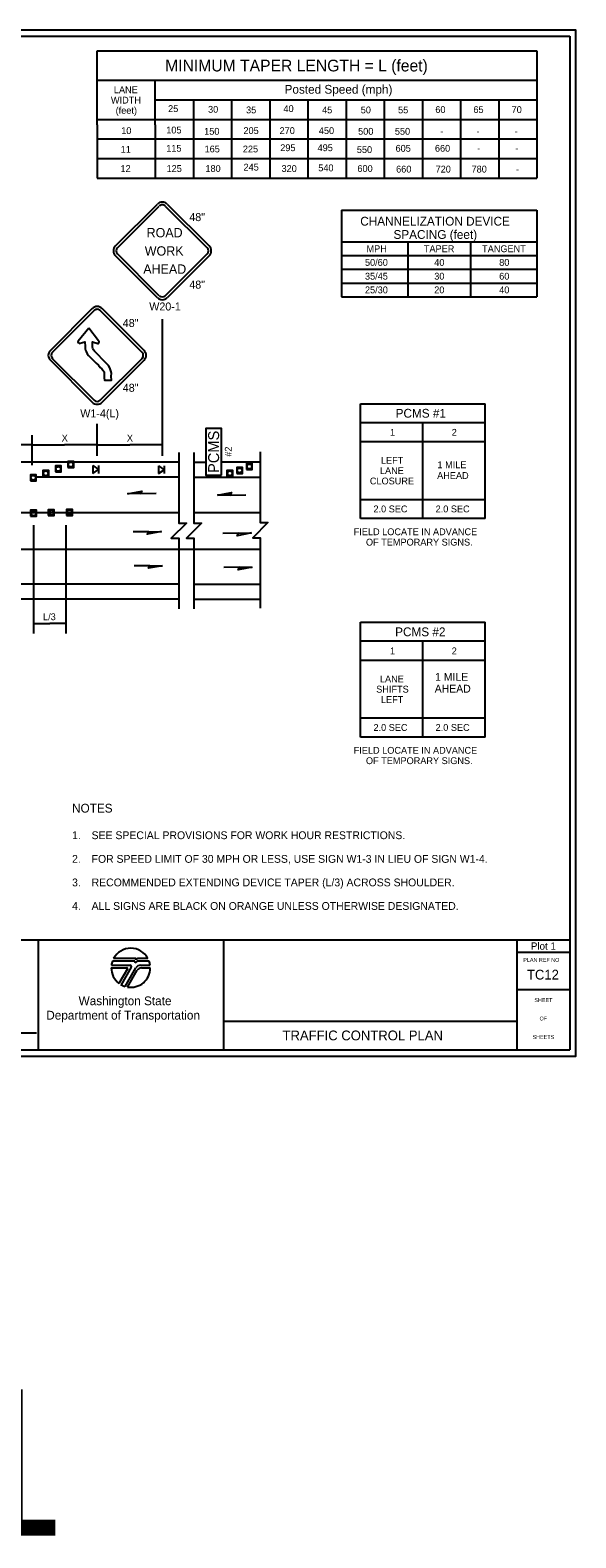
# Model space of a CAD drawing. Extents: x 99988 to 100172, y 99995 to 100047.
# Drawn here: x 100010.23 to 100015.81, y 99995.01 to 100010.44 of the extents above; entities that cross this region are included whole.
import ezdxf

# ---------------------------------------------------------------- set-up
doc = ezdxf.new("R2010")
doc.units = 0
for name, color, linetype in [('Default', 7, 'Continuous'), ('Level 15', 7, 'Continuous'), ('Level 20', 7, 'Continuous'), ('SH_DE_DetailBody1Text', 7, 'Continuous'), ('SH_GI_PlotLimits', 7, 'Continuous'), ('SH_GI_SheetBorder', 7, 'Continuous'), ('SH_GI_SheetLocationText', 7, 'Continuous'), ('SH_GI_SheetTextInCells', 7, 'Continuous'), ('SH_GI_TitleBlockText', 7, 'Continuous'), ('SH_GI_TrafficMvmntArrowRt1Lane', 7, 'Continuous'), ('SH_GI_WSDOTLogo', 7, 'Continuous'), ('SH_TI_ChanSpacing25to70Note', 7, 'Continuous'), ('SH_TI_MinTaperLength25to60Note', 7, 'Continuous'), ('TR_SN_WarningSigns', 7, 'Continuous'), ('TR_WZ_PortableChangeMessageSign', 7, 'Continuous'), ('TR_WZ_TrafficSafetyCone', 7, 'Continuous'), ('TR_WZ_WorkZoneDetails', 7, 'Continuous')]:
    doc.layers.add(name, color=color, linetype=linetype)

msp = doc.modelspace()

# ---------------------------------------------------------------- linework, layer by layer
at = {"layer": 'Default'}
for p, q in [((100010.867, 100005.98), (100010.925, 100005.94)), ((100010.867, 100005.98), (100010.867, 100005.9)), ((100010.925, 100005.98), (100010.925, 100005.9)), ((100011.54, 100005.979), (100011.598, 100005.938)), ((100011.54, 100005.979), (100011.54, 100005.898)), ((100011.598, 100005.979), (100011.598, 100005.898)), ((100010.867, 100005.9), (100010.925, 100005.94)), ((100011.54, 100005.898), (100011.598, 100005.938)), ((100011.748, 100005.496), (100005.446, 100005.496)), ((100012.582, 100005.496), (100011.903, 100005.496)), ((100012.582, 100005.121), (100002.425, 100005.121))]:
    msp.add_line(p, q, dxfattribs=at)
at = {"layer": 'Level 15'}
for p, q in [((100010.247, 100006.192), (100009.857, 100006.192)), ((100010.247, 100006.192), (100010.58, 100006.192)), ((100010.913, 100006.192), (100010.58, 100006.192)), ((100010.913, 100006.192), (100011.247, 100006.192)), ((100011.58, 100006.192), (100011.247, 100006.192)), ((100010.263, 100004.363), (100010.429, 100004.363)), ((100010.596, 100004.363), (100010.429, 100004.363))]:
    msp.add_line(p, q, dxfattribs=at)
at = {"layer": 'SH_GI_PlotLimits'}
msp.add_lwpolyline([(99999.312, 99999.937), (100015.812, 99999.937), (100015.812, 100010.437), (99999.312, 100010.437)], close=True, dxfattribs=at)
at = {"layer": 'SH_GI_SheetBorder'}
for p, q in [((100000, 100010.375), (100015.75, 100010.375)), ((100015.75, 100010.375), (100015.75, 100000)), ((100000, 100001.126), (100015.75, 100001.126)), ((100010.309, 100001.126), (100010.309, 100000)), ((100012.205, 100001.126), (100012.205, 100000)), ((100015.208, 100001.126), (100015.208, 100000)), ((100015.208, 100001.001), (100015.75, 100001.001)), ((100015.208, 100000.618), (100015.75, 100000.618)), ((100012.205, 100000.295), (100015.208, 100000.295)), ((100009.78, 100000.173), (100010.291, 100000.173)), ((100000, 100000), (100015.75, 100000))]:
    msp.add_line(p, q, dxfattribs=at)
at = {"layer": 'SH_GI_TrafficMvmntArrowRt1Lane'}
for p, q in [((100011.355, 100005.694), (100011.516, 100005.697)), ((100012.274, 100005.679), (100012.435, 100005.682)), ((100011.441, 100005.304), (100011.28, 100005.302)), ((100012.36, 100005.289), (100012.199, 100005.287)), ((100011.451, 100004.955), (100011.29, 100004.953)), ((100012.37, 100004.94), (100012.209, 100004.937))]:
    msp.add_line(p, q, dxfattribs=at)
for points in [[(100011.224, 100005.693), (100011.37, 100005.72), (100011.355, 100005.694)], [(100012.143, 100005.678), (100012.289, 100005.705), (100012.274, 100005.679)], [(100011.572, 100005.306), (100011.426, 100005.278), (100011.441, 100005.304)], [(100012.491, 100005.291), (100012.345, 100005.263), (100012.36, 100005.289)], [(100011.582, 100004.956), (100011.437, 100004.929), (100011.451, 100004.955)], [(100012.501, 100004.941), (100012.355, 100004.914), (100012.37, 100004.94)]]:
    msp.add_lwpolyline(points, close=True, dxfattribs=at)
at = {"layer": 'SH_GI_WSDOTLogo'}
for p, q in [((100011.289, 100000.909), (100011.07, 100000.909)), ((100011.303, 100000.935), (100011.081, 100000.935)), ((100011.433, 100000.935), (100011.335, 100000.935)), ((100011.445, 100000.909), (100011.343, 100000.909)), ((100011.343, 100000.909), (100011.343, 100000.909)), ((100011.057, 100000.84), (100011.215, 100000.84)), ((100011.059, 100000.866), (100011.25, 100000.866)), ((100011.222, 100000.828), (100011.136, 100000.681)), ((100011.261, 100000.846), (100011.157, 100000.667)), ((100011.199, 100000.649), (100011.309, 100000.839)), ((100011.224, 100000.643), (100011.324, 100000.816)), ((100011.356, 100000.866), (100011.456, 100000.866)), ((100011.365, 100000.839), (100011.457, 100000.839))]:
    msp.add_line(p, q, dxfattribs=at)
for centre, radius, start, end in [((100011.257, 100000.84), 0.2, 28.4787, 151.532), ((100011.257, 100000.84), 0.2, 159.696, 172.5057), ((100011.289, 100000.895), 0.0148, 327.8418, 89.9985), ((100011.343, 100000.861), 0.0484, 89.9953, 147.8238), ((100011.303, 100000.926), 0.00903, 329.8742, 90.0033), ((100011.335, 100000.907), 0.0287, 90.0072, 148.1676), ((100011.257, 100000.84), 0.2, 7.4943, 20.2941), ((100011.257, 100000.84), 0.2, 179.9986, 232.8433), ((100011.215, 100000.832), 0.0082, 329.7436, 90), ((100011.257, 100000.84), 0.2, 260.5455, 359.8086), ((100011.25, 100000.853), 0.0131, 329.7683, 90), ((100011.356, 100000.812), 0.0542, 90, 149.9974), ((100011.365, 100000.792), 0.0476, 90, 150.0543), ((100011.257, 100000.84), 0.2, 239.7929, 253.0448)]:
    msp.add_arc(centre, radius, start, end, dxfattribs=at)
at = {"layer": 'SH_TI_ChanSpacing25to70Note'}
for p, q in [((100013.414, 100008.595), (100013.414, 100007.709)), ((100013.414, 100008.595), (100015.414, 100008.595)), ((100015.414, 100008.595), (100015.414, 100007.709)), ((100013.414, 100008.27), (100015.414, 100008.27)), ((100014.097, 100007.709), (100014.097, 100008.27)), ((100014.739, 100007.709), (100014.739, 100008.27)), ((100013.414, 100008.13), (100015.414, 100008.13)), ((100013.414, 100007.99), (100015.414, 100007.99)), ((100013.414, 100007.849), (100015.414, 100007.849)), ((100013.414, 100007.709), (100015.414, 100007.709))]:
    msp.add_line(p, q, dxfattribs=at)
at = {"layer": 'SH_TI_MinTaperLength25to60Note'}
for p, q in [((100010.914, 100010.227), (100015.414, 100010.227)), ((100010.914, 100009.469), (100010.914, 100010.227)), ((100015.414, 100010.227), (100015.414, 100008.924)), ((100010.914, 100009.924), (100015.414, 100009.924)), ((100011.507, 100009.469), (100011.507, 100009.924)), ((100011.507, 100009.724), (100015.414, 100009.724)), ((100011.898, 100009.724), (100011.898, 100008.924)), ((100012.288, 100009.724), (100012.288, 100008.924)), ((100012.679, 100009.724), (100012.679, 100008.924)), ((100013.07, 100009.724), (100013.07, 100008.924)), ((100013.46, 100009.724), (100013.46, 100008.924)), ((100013.851, 100009.724), (100013.851, 100008.924)), ((100014.242, 100009.724), (100014.242, 100008.924)), ((100014.632, 100009.724), (100014.632, 100008.924)), ((100015.023, 100009.724), (100015.023, 100008.924)), ((100010.914, 100009.524), (100015.414, 100009.524)), ((100010.914, 100009.469), (100010.914, 100008.924)), ((100011.507, 100009.469), (100011.507, 100008.924)), ((100010.914, 100009.324), (100015.414, 100009.324)), ((100010.914, 100009.124), (100015.414, 100009.124)), ((100010.914, 100008.924), (100015.414, 100008.924))]:
    msp.add_line(p, q, dxfattribs=at)
at = {"layer": 'TR_SN_WarningSigns'}
for p, q in [((100011.1, 100008.229), (100011.529, 100008.657)), ((100011.121, 100008.209), (100011.549, 100008.637)), ((100011.61, 100008.637), (100012.039, 100008.209)), ((100011.631, 100008.657), (100012.059, 100008.229)), ((100011.549, 100007.719), (100011.121, 100008.148)), ((100012.039, 100008.148), (100011.61, 100007.719)), ((100011.529, 100007.699), (100011.1, 100008.127)), ((100012.059, 100008.127), (100011.631, 100007.699)), ((100010.862, 100007.588), (100010.434, 100007.16)), ((100010.883, 100007.568), (100010.454, 100007.139)), ((100011.372, 100007.139), (100010.944, 100007.568)), ((100011.393, 100007.16), (100010.964, 100007.588)), ((100010.434, 100007.058), (100010.862, 100006.63)), ((100010.454, 100007.078), (100010.883, 100006.65)), ((100010.944, 100006.65), (100011.372, 100007.078)), ((100010.964, 100006.63), (100011.393, 100007.058))]:
    msp.add_line(p, q, dxfattribs=at)
msp.add_lwpolyline([(100010.828, 100007.386), (100010.718, 100007.254), (100010.716, 100007.247), (100010.721, 100007.237), (100010.731, 100007.229), (100010.74, 100007.232), (100010.788, 100007.246), (100010.789, 100007.198), (100010.79, 100007.176), (100010.794, 100007.162), (100010.799, 100007.149), (100010.812, 100007.126), (100010.825, 100007.109), (100010.84, 100007.09), (100010.859, 100007.073), (100010.88, 100007.052), (100010.903, 100007.028), (100010.925, 100007.007), (100010.945, 100006.986), (100010.962, 100006.97), (100010.976, 100006.954), (100010.983, 100006.941), (100010.986, 100006.923), (100010.983, 100006.897), (100010.985, 100006.88), (100010.987, 100006.856), (100011.059, 100006.856), (100011.057, 100006.896), (100011.059, 100006.922), (100011.056, 100006.94), (100011.05, 100006.96), (100011.042, 100006.982), (100011.029, 100007.006), (100011.005, 100007.03), (100010.886, 100007.153), (100010.874, 100007.167), (100010.868, 100007.178), (100010.866, 100007.192), (100010.864, 100007.201), (100010.865, 100007.247), (100010.919, 100007.229), (100010.925, 100007.231), (100010.93, 100007.236), (100010.935, 100007.247), (100010.934, 100007.252), (100010.927, 100007.258)], close=True, dxfattribs=at)
for centre, radius, start, end in [((100011.58, 100008.606), 0.0721, 44.9963, 134.9997), ((100011.58, 100008.606), 0.0433, 44.9963, 134.9997), ((100011.151, 100008.178), 0.0721, 134.9966, 224.9936), ((100011.151, 100008.178), 0.0433, 134.9966, 224.9936), ((100012.008, 100008.178), 0.0433, 314.9994, 44.9948), ((100012.008, 100008.178), 0.0721, 314.9994, 44.9948), ((100011.58, 100007.75), 0.0721, 225, 314.9996), ((100011.58, 100007.75), 0.0433, 225, 314.9996), ((100010.913, 100007.537), 0.0721, 44.9963, 134.9997), ((100010.913, 100007.537), 0.0433, 44.9963, 134.9997), ((100010.485, 100007.109), 0.0721, 134.9966, 224.9936), ((100010.485, 100007.109), 0.0433, 134.9966, 224.9936), ((100011.342, 100007.109), 0.0433, 314.9994, 44.9948), ((100011.342, 100007.109), 0.0721, 314.9994, 44.9948), ((100010.913, 100006.681), 0.0721, 225, 314.9996), ((100010.913, 100006.681), 0.0433, 225, 314.9996)]:
    msp.add_arc(centre, radius, start, end, dxfattribs=at)
at = {"layer": 'TR_WZ_PortableChangeMessageSign'}
msp.add_lwpolyline([(100012.185, 100005.881), (100012.185, 100006.361), (100012.025, 100006.361), (100012.025, 100005.881)], close=True, dxfattribs=at)
at = {"layer": 'TR_WZ_TrafficSafetyCone'}
for points in [[(100010.485, 100005.916), (100010.545, 100005.916), (100010.545, 100005.977), (100010.485, 100005.977)], [(100010.613, 100005.962), (100010.674, 100005.962), (100010.674, 100006.023), (100010.613, 100006.023)], [(100012.44, 100005.941), (100012.501, 100005.941), (100012.501, 100006.001), (100012.44, 100006.001)], [(100010.229, 100005.825), (100010.29, 100005.825), (100010.29, 100005.886), (100010.229, 100005.886)], [(100010.356, 100005.871), (100010.417, 100005.871), (100010.417, 100005.931), (100010.356, 100005.931)], [(100012.241, 100005.87), (100012.302, 100005.87), (100012.302, 100005.931), (100012.241, 100005.931)], [(100012.341, 100005.901), (100012.401, 100005.901), (100012.401, 100005.962), (100012.341, 100005.962)], [(100010.232, 100005.462), (100010.293, 100005.462), (100010.293, 100005.523), (100010.232, 100005.523)], [(100010.413, 100005.468), (100010.474, 100005.468), (100010.474, 100005.529), (100010.413, 100005.529)], [(100010.599, 100005.471), (100010.66, 100005.471), (100010.66, 100005.531), (100010.599, 100005.531)]]:
    msp.add_lwpolyline(points, close=True, dxfattribs=at)
for centre in [(100010.643, 100005.992), (100012.471, 100005.971), (100010.259, 100005.856), (100010.387, 100005.901), (100010.515, 100005.947), (100012.272, 100005.901), (100012.371, 100005.931), (100010.263, 100005.492), (100010.444, 100005.499), (100010.629, 100005.501)]:
    msp.add_circle(centre, 0.0244, dxfattribs=at)
at = {"layer": 'TR_WZ_WorkZoneDetails'}
for p, q in [((100011.58, 100006.08), (100011.58, 100007.478)), ((100013.61, 100006.614), (100014.883, 100006.614)), ((100013.61, 100005.439), (100013.61, 100006.614)), ((100014.883, 100005.439), (100014.883, 100006.614)), ((100010.247, 100005.986), (100010.247, 100006.292)), ((100010.913, 100006.08), (100010.913, 100006.408)), ((100014.883, 100006.418), (100013.61, 100006.418)), ((100014.246, 100005.439), (100014.246, 100006.418)), ((100014.883, 100006.223), (100013.61, 100006.223)), ((100011.748, 100006.014), (100008.204, 100006.014)), ((100011.903, 100006.014), (100012.019, 100006.014)), ((100012.195, 100006.02), (100012.582, 100006.02)), ((100011.748, 100005.861), (100010.29, 100005.861)), ((100011.903, 100005.861), (100012.577, 100005.861)), ((100013.61, 100005.635), (100014.883, 100005.635)), ((100010.263, 100004.263), (100010.263, 100005.371)), ((100010.596, 100004.263), (100010.596, 100005.371)), ((100014.883, 100005.439), (100013.61, 100005.439)), ((100011.748, 100004.768), (100002.428, 100004.768)), ((100011.903, 100004.768), (100012.584, 100004.768)), ((100011.748, 100004.614), (100002.431, 100004.614)), ((100011.903, 100004.614), (100012.581, 100004.614)), ((100013.61, 100004.377), (100014.883, 100004.377)), ((100013.61, 100003.202), (100013.61, 100004.377)), ((100014.883, 100003.202), (100014.883, 100004.377)), ((100014.883, 100004.182), (100013.61, 100004.182)), ((100014.246, 100003.202), (100014.246, 100004.182)), ((100014.883, 100003.986), (100013.61, 100003.986)), ((100013.61, 100003.398), (100014.883, 100003.398)), ((100014.883, 100003.202), (100013.61, 100003.202))]:
    msp.add_line(p, q, dxfattribs=at)
for points in [[(100011.748, 100006.114), (100011.748, 100005.392), (100011.826, 100005.392), (100011.671, 100005.237), (100011.748, 100005.237), (100011.748, 100004.514)], [(100011.903, 100006.114), (100011.903, 100005.392), (100011.981, 100005.392), (100011.826, 100005.237), (100011.903, 100005.237), (100011.903, 100004.514)], [(100012.582, 100006.12), (100012.582, 100005.397), (100012.659, 100005.397), (100012.505, 100005.242), (100012.582, 100005.242), (100012.582, 100004.52)]]:
    msp.add_lwpolyline(points, dxfattribs=at)

# ---------------------------------------------------------------- texts
at = {"layer": 'Level 20'}
for s, height, p in [('X', 0.07, (100010.55, 100006.227)), ('L/3', 0.07, (100010.359, 100004.398)), ('NOTES', 0.09, (100010.656, 100002.429)), ('1.', 0.08, (100010.656, 100002.157)), ('SEE SPECIAL PROVISIONS FOR WORK HOUR RESTRICTIONS.', 0.08, (100010.856, 100002.157)), ('2.', 0.08, (100010.656, 100001.915)), ('FOR SPEED LIMIT OF 30 MPH OR LESS, USE SIGN W1-3 IN LIEU OF SIGN W1-4.', 0.08, (100010.856, 100001.915)), ('3.', 0.08, (100010.656, 100001.674)), ('RECOMMENDED EXTENDING DEVICE TAPER (L/3) ACROSS SHOULDER.', 0.08, (100010.856, 100001.674)), ('4.', 0.08, (100010.656, 100001.433)), ('ALL SIGNS ARE BLACK ON ORANGE UNLESS OTHERWISE DESIGNATED.', 0.08, (100010.856, 100001.433))]:
    msp.add_text(s, height=height, dxfattribs=at).set_placement(p)
for s, rotation, p in [('X', 360, (100011.217, 100006.227)), ('#2', 90, (100012.29, 100006.071))]:
    msp.add_text(s, height=0.07, rotation=rotation, dxfattribs=at).set_placement(p)
at = {"layer": 'SH_DE_DetailBody1Text'}
for s, height, p in [('PCMS #1', 0.09, (100013.968, 100006.471)), ('1', 0.07, (100013.91, 100006.286)), ('2', 0.07, (100014.542, 100006.286)), ('LEFT', 0.07, (100013.818, 100005.999)), ('1 MILE', 0.07, (100014.396, 100005.954)), ('CLOSURE', 0.07, (100013.704, 100005.788)), ('LANE', 0.07, (100013.807, 100005.894)), ('AHEAD', 0.07, (100014.393, 100005.844)), ('2.0 SEC', 0.07, (100013.741, 100005.502)), ('2.0 SEC', 0.07, (100014.377, 100005.502)), ('FIELD LOCATE IN ADVANCE', 0.07, (100013.539, 100005.268)), ('OF TEMPORARY SIGNS.', 0.07, (100013.664, 100005.162)), ('PCMS #2', 0.09, (100013.963, 100004.234)), ('1', 0.07, (100013.91, 100004.049)), ('2', 0.07, (100014.542, 100004.049)), ('LANE', 0.07, (100013.807, 100003.762)), ('1 MILE', 0.08, (100014.372, 100003.778)), ('SHIFTS', 0.07, (100013.769, 100003.657)), ('AHEAD', 0.08, (100014.368, 100003.657)), ('LEFT', 0.07, (100013.818, 100003.551)), ('2.0 SEC', 0.07, (100013.741, 100003.265)), ('2.0 SEC', 0.07, (100014.377, 100003.265)), ('FIELD LOCATE IN ADVANCE', 0.07, (100013.539, 100003.031)), ('OF TEMPORARY SIGNS.', 0.07, (100013.664, 100002.925))]:
    msp.add_text(s, height=height, dxfattribs=at).set_placement(p)
at = {"layer": 'SH_GI_SheetBorder'}
msp.add_text('PLAN REF NO', height=0.04003, dxfattribs=at).set_placement((100015.275, 100000.901))
at = {"layer": 'SH_GI_SheetLocationText'}
for height, p in [(0.075, (100015.352, 100001.025)), (1.5, (100005.455, 99995.027))]:
    msp.add_text('Plot 1', height=height, dxfattribs=at).set_placement(p)
at = {"layer": 'SH_GI_SheetTextInCells'}
for s, height, p in [('Washington State', 0.09007, (100010.723, 100000.457)), ('SHEET', 0.04, (100015.388, 100000.49)), ('Department of Transportation', 0.09007, (100010.392, 100000.31)), ('OF', 0.04, (100015.441, 100000.301)), ('SHEETS', 0.04, (100015.37, 100000.112))]:
    msp.add_text(s, height=height, dxfattribs=at).set_placement(p)
at = {"layer": 'SH_GI_TitleBlockText'}
for s, p in [('TC12', (100015.312, 100000.72)), ('TRAFFIC CONTROL PLAN', (100012.81, 100000.098))]:
    msp.add_text(s, height=0.1, dxfattribs=at).set_placement(p)
at = {"layer": 'SH_TI_ChanSpacing25to70Note'}
for s, height, p in [('CHANNELIZATION DEVICE', 0.09, (100013.606, 100008.437)), ('SPACING (feet)', 0.09, (100013.946, 100008.301)), ('MPH', 0.07, (100013.67, 100008.165)), ('TAPER', 0.07, (100014.257, 100008.165)), ('TANGENT', 0.07, (100014.853, 100008.165)), ('50/60', 0.07, (100013.654, 100008.025)), ('40', 0.07, (100014.363, 100008.025)), ('80', 0.07, (100015.028, 100008.025)), ('35/45', 0.07, (100013.654, 100007.884)), ('30', 0.07, (100014.363, 100007.884)), ('60', 0.07, (100015.028, 100007.884)), ('25/30', 0.07, (100013.654, 100007.744)), ('20', 0.07, (100014.363, 100007.744)), ('40', 0.07, (100015.028, 100007.744))]:
    msp.add_text(s, height=height, dxfattribs=at).set_placement(p)
at = {"layer": 'SH_TI_MinTaperLength25to60Note'}
for s, height, p in [('MINIMUM TAPER LENGTH = L (feet)', 0.12, (100011.609, 100010.015)), ('LANE', 0.07, (100011.084, 100009.792)), ('Posted Speed (mph)', 0.09, (100012.831, 100009.787)), ('WIDTH', 0.07, (100011.054, 100009.686)), ('(feet)', 0.07, (100011.102, 100009.581)), ('25', 0.07, (100011.639, 100009.599)), ('30', 0.07, (100012.048, 100009.592)), ('35', 0.07, (100012.437, 100009.586)), ('40', 0.07, (100012.82, 100009.599)), ('45', 0.07, (100013.215, 100009.586)), ('50', 0.07, (100013.611, 100009.586)), ('55', 0.07, (100013.993, 100009.586)), ('60', 0.07, (100014.374, 100009.589)), ('65', 0.07, (100014.764, 100009.589)), ('70', 0.07, (100015.155, 100009.589)), ('10', 0.07, (100011.159, 100009.374)), ('105', 0.07, (100011.62, 100009.38)), ('150', 0.07, (100012.008, 100009.367)), ('205', 0.07, (100012.41, 100009.374)), ('270', 0.07, (100012.78, 100009.374)), ('450', 0.07, (100013.182, 100009.374)), ('500', 0.07, (100013.584, 100009.367)), ('550', 0.07, (100013.96, 100009.367)), ('-', 0.07, (100014.426, 100009.367)), ('-', 0.07, (100014.795, 100009.367)), ('-', 0.07, (100015.186, 100009.367)), ('11', 0.07, (100011.154, 100009.182)), ('115', 0.07, (100011.62, 100009.193)), ('165', 0.07, (100012.012, 100009.186)), ('225', 0.07, (100012.404, 100009.186)), ('295', 0.07, (100012.787, 100009.199)), ('495', 0.07, (100013.169, 100009.199)), ('550', 0.07, (100013.571, 100009.18)), ('605', 0.07, (100013.967, 100009.193)), ('660', 0.07, (100014.37, 100009.193)), ('-', 0.07, (100014.802, 100009.193)), ('-', 0.07, (100015.193, 100009.193)), ('245', 0.07, (100012.411, 100009)), ('540', 0.07, (100013.176, 100008.993)), ('12', 0.07, (100011.152, 100008.986)), ('125', 0.07, (100011.623, 100008.986)), ('180', 0.07, (100012.021, 100008.986)), ('320', 0.07, (100012.8, 100008.986)), ('600', 0.07, (100013.577, 100008.986)), ('660', 0.07, (100013.973, 100008.98)), ('720', 0.07, (100014.377, 100008.98)), ('780', 0.07, (100014.745, 100008.98)), ('-', 0.07, (100015.199, 100008.98))]:
    msp.add_text(s, height=height, dxfattribs=at).set_placement(p)
at = {"layer": 'TR_SN_WarningSigns'}
for s, height, p in [('48"', 0.082, (100011.856, 100008.483)), ('ROAD', 0.0954, (100011.419, 100008.317)), ('WORK', 0.0954, (100011.4, 100008.13)), ('AHEAD', 0.0954, (100011.385, 100007.944)), ('48"', 0.082, (100011.856, 100007.792)), ('W20-1', 0.082, (100011.446, 100007.568)), ('48"', 0.082, (100011.175, 100007.399)), ('48"', 0.082, (100011.175, 100006.736)), ('W1-4(L)', 0.082, (100010.74, 100006.474))]:
    msp.add_text(s, height=height, dxfattribs=at).set_placement(p)
at = {"layer": 'TR_WZ_PortableChangeMessageSign'}
msp.add_text('PCMS', height=0.112, rotation=90, dxfattribs=at).set_placement((100012.161, 100005.905))

doc.saveas('drawing.dxf')
